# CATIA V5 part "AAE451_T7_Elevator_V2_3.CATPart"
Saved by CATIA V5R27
Part number: Elevator
Bounding box of the stored display mesh (mm): x 0 to 69.698, y -12.436 to 0.05, z -0.005 to 114.975
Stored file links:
  W:\AAE 451\AAE451_T7_TailAssembly_V2\AAE451_T7_Elevator_V2_3.CATPart
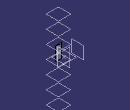
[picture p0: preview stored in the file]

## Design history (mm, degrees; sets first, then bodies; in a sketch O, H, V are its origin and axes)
Set1 "GeometryFromExcel"
  Point1: (1, 0.001, 0)
  Point2: (0.95, 0.0067, 0)
  Point3: (0.9, 0.0121, 0)
  Point4: (0.8, 0.0219, 0)
  Point5: (0.7, 0.0305, 0)
  Point6: (0.6, 0.038, 0)
  Point7: (0.5, 0.0441, 0)
  Point8: (0.4, 0.0484, 0)
  Point9: (0.3, 0.05, 0)
  Point10: (0.25, 0.0495, 0)
  Point11: (0.2, 0.0478, 0)
  Point12: (0.15, 0.0445, 0)
  Point13: (0.1, 0.039, 0)
  Point14: (0.075, 0.035, 0)
  Point15: (0.05, 0.0296, 0)
  Point16: (0.025, 0.0218, 0)
  Point17: (0.0125, 0.0158, 0)
  Point18: (0, 0, 0)
  Point19: (0.0125, -0.0158, 0)
  Point20: (0.025, -0.0218, 0)
  Point21: (0.05, -0.0296, 0)
  Point22: (0.075, -0.035, 0)
  Point23: (0.1, -0.039, 0)
  Point24: (0.15, -0.0445, 0)
  Point25: (0.2, -0.0478, 0)
  Point26: (0.25, -0.0495, 0)
  Point27: (0.3, -0.05, 0)
  Point28: (0.4, -0.0484, 0)
  Point29: (0.5, -0.0441, 0)
  Point30: (0.6, -0.038, 0)
  Point31: (0.7, -0.0305, 0)
  Point32: (0.8, -0.0219, 0)
  Point33: (0.9, -0.0121, 0)
  Point34: (0.95, -0.0067, 0)
  Point35: (1, -0.001, 0)
  Point36: (1, 0.001, 0)
  Point37: (0.95, 0.0067, 0)
  Point38: (0.9, 0.0121, 0)
  Point39: (0.8, 0.0219, 0)
  Point40: (0.7, 0.0305, 0)
  Point41: (0.6, 0.038, 0)
  Point42: (0.5, 0.0441, 0)
  Point43: (0.4, 0.0484, 0)
  Point44: (0.3, 0.05, 0)
  Point45: (0.25, 0.0495, 0)
  Point46: (0.2, 0.0478, 0)
  Point47: (0.15, 0.0445, 0)
  Point48: (0.1, 0.039, 0)
  Point49: (0.075, 0.035, 0)
  Point50: (0.05, 0.0296, 0)
  Point51: (0.025, 0.0218, 0)
  Point52: (0.0125, 0.0158, 0)
  Point53: (0, 0, 0)
  Point54: (0.0125, -0.0158, 0)
  Point55: (0.025, -0.0218, 0)
  Point56: (0.05, -0.0296, 0)
  Point57: (0.075, -0.035, 0)
  Point58: (0.1, -0.039, 0)
  Point59: (0.15, -0.0445, 0)
  Point60: (0.2, -0.0478, 0)
  Point61: (0.25, -0.0495, 0)
  Point62: (0.3, -0.05, 0)
  Point63: (0.4, -0.0484, 0)
  Point64: (0.5, -0.0441, 0)
  Point65: (0.6, -0.038, 0)
  Point66: (0.7, -0.0305, 0)
  Point67: (0.8, -0.0219, 0)
  Point68: (0.9, -0.0121, 0)
  Point69: (0.95, -0.0067, 0)
  Point70: (1, -0.001, 0)
  Curve1: Elements (Point36; Point37; Point38; Point39; Point40; Point41; Point42; Point43; Point44; Point45; Point46; Point47; Point48; Point49; Point50; Point51; Point52; Point53; Point54; Point55; Point56; Point57; Point58; Point59; Point60; Point61; Point62; Point63; Point64; Point65; Point66; Point67; Point68; Point69; Point70)
  Sketch1 on xy-plane, origin (0, 0, 0), H (1, 0, 0), V (0, 1, 0)
    projected curve E1 from edge of Curve1
    point P1 (1, 0.0011)
    line L1 (1, 0.0011) -> (1, -0.001)
    point P3 (1, 0.001)
    point P4 (1, -0.001)
    reference projected point E2 (1, 0.001) from Point1
    reference projected point E3 (1, -0.001) from Point35
    coincidence: P3 E2, P4 E3, P1 P3
Body1 (main body)
  Pad1: profile Sketch1, direction (0, 0, 1), length 1.5215, mirrored extent
  Scaling1: Reference Point40, Ratio 230, ToTransfor Pad1
  Plane1: type Offset, RefPlane yz-plane, Offset 120, reversed
  Sketch2 on xy-plane, origin (0, 0, 0), H (1, 0, 0), V (0, 1, 0)
    reference projected line E1 (69.6979, -7.2245) -> (69.698, -6.7499) from edge [face of Pad1 from Sketch1.L1 | end face of Pad1]
    line L1 (13.6994, -1.0636) -> (13.6965, -12.9194)
    projected curve E2 from edge [face of Pad1 from Sketch1.E1 | end face of Pad1]
    projected curve E3 from edge [face of Pad1 from Sketch1.E1 | end face of Pad1]
    distance E1 L1 = 56
  Pocket1: profile Sketch2, direction (0, 0, -1), through (limit type 3), opposite side through (limit type 3)
  Fillet1: radius 5, on edge [face of Pad1 from Sketch1.E1 | face of Pocket1 from Sketch2.L1]; edge [face of Pocket1 from Sketch2.L1 | face of Pad1 from Sketch1.E1]
  Sketch3 on zx-plane, origin (0, 0, 0), H (-1, 0, 0), V (0, 0, 1)
    line L1 (-135.4649, -344.945) -> (50.2623, -344.945)
    line L2 (50.2623, -344.945) -> (50.2623, -349.945)
    line L3 (50.2623, -349.945) -> (-135.4649, -349.945)
    line L4 (-135.4649, -349.945) -> (-135.4649, -344.945)
    line L5 (-146.4826, 349.945) -> (56.5582, 349.945)
    line L6 (56.5582, 349.945) -> (56.5582, 344.945)
    line L7 (56.5582, 344.945) -> (-146.4826, 344.945)
    line L8 (-146.4826, 344.945) -> (-146.4826, 349.945)
    reference projected line E1 (-69.7, 349.945) -> (160.3, 349.945) from edge [face of Pad1 from Sketch1.E1 | end face of Pad1]
    reference projected line E2 (-69.7, -349.945) -> (160.3, -349.945) from edge [start face of Pad1 | face of Pad1 from Sketch1.E1]
    distance L7 L5 = 5
    horizontal: L1 H, L3 H, L5 H, L7 H
    vertical: L2 V, L4 V, L6 V, L8 V
    coincidence: L5 E1, L3 E2
    symmetry: L7 L1 H
  Pocket2: profile Sketch3, direction (0, -1, 0), through (limit type 3)
  Sketch4 on face of Pocket1 from Sketch2.L1, origin (13.6996, -0.0033, 0), H (-0.0002, -1, 0), V (0, 0, 1)
    line L1 (6.4867, 8) -> (7.4867, 8)
    line L2 (7.4867, 8) -> (7.4867, -8)
    line L3 (7.4867, -8) -> (6.4867, -8)
    line L4 (6.4867, -8) -> (6.4867, 8)
    construction line L5 (6.9867, 7.1913) -> (6.9867, -6.7162)
    reference projected line E1 (1.5418, 344.945) -> (1.5418, -344.945) from edge [face of Pad1 from Sketch1.E1 | face of Fillet1]
    reference projected line E2 (12.4317, 344.945) -> (12.4317, -344.945) from edge [face of Fillet1 | face of Pad1 from Sketch1.E1]
    distance L4 L2 = 1
    distance L1 L3 = 16
    horizontal: L1 H, L3 H
    vertical: L2 V, L4 V
    symmetry: L3 L1 H, L4 L2 L5, E1 E2 L5
  Pocket3: profile Sketch4, direction (1, -0.0002, 0), length 13.7
  RectPattern1: of Pocket3, direction 1 instances 2, spacing 230, along zx-plane
  Mirror1: of RectPattern1, about xy-plane
  Plane2: type Offset, RefPlane face of Pocket2 from Sketch3.L7, Offset 0, reversed
  Plane3: type Offset, RefPlane face of Pocket2 from Sketch3.L1, Offset 0, reversed
  Plane4: type Offset, RefPlane Plane3, Offset 114.98
  Plane5: type Offset, RefPlane Plane4, Offset 114.98
  Plane6: type Offset, RefPlane Plane5, Offset 114.98
  Plane7: type Offset, RefPlane Plane6, Offset 114.98
  Plane8: type Offset, RefPlane Plane7, Offset 114.98
  Split1: SplitPlane Plane6
  Split2: SplitPlane Plane7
